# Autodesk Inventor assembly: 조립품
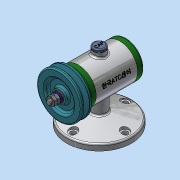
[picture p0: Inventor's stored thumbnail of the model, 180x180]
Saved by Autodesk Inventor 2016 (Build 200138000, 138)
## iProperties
Created: 2018-12
Part Number: 조립품
Material: 일반
Document SubType Name: Assembly
Designer: Administrator
Author: Administrator
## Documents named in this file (15)
- C:\Users\Administrator\Desktop\481207V1050\조립품.iam
- C:\Users\Administrator\Desktop\481207V1050\본체.ipt
- C:\Users\Administrator\Desktop\481207V1050\베어링 15 x 32 x 9.ipt
- C:\Users\Administrator\Desktop\481207V1050\고무캡.ipt
- C:\Users\Administrator\Desktop\481207V1050\축.ipt
- C:\Users\Administrator\Desktop\481207V1050\뒤커버.ipt
- C:\Users\Administrator\Desktop\481207V1050\앞커버.ipt
- C:\Users\Administrator\Desktop\481207V1050\볼트 M4 x 12.ipt
- C:\Users\Administrator\Desktop\481207V1050\오일 실 15 25 7.ipt
- C:\Users\Administrator\Desktop\481207V1050\키 3 x 3 x 12.ipt
- C:\Users\Administrator\Desktop\481207V1050\V벨트풀리.ipt
- C:\Users\Administrator\Desktop\481207V1050\스프링와셔 8.ipt
- C:\Users\Administrator\Desktop\481207V1050\와셔 8x17.ipt
- C:\Users\Administrator\Desktop\481207V1050\너트 M8.ipt
- 너트 M8.ipt
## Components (2 placed, 2 different names)
1. 고무캡:1 — 각도:2, 각도:4
2. V벨트풀리:1 — 각도:3
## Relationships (3: Angle 3)
- 각도:2 [Angle]: 고무캡:1
- 각도:3 [Angle]: V벨트풀리:1
- 각도:4 [Angle]: 고무캡:1
